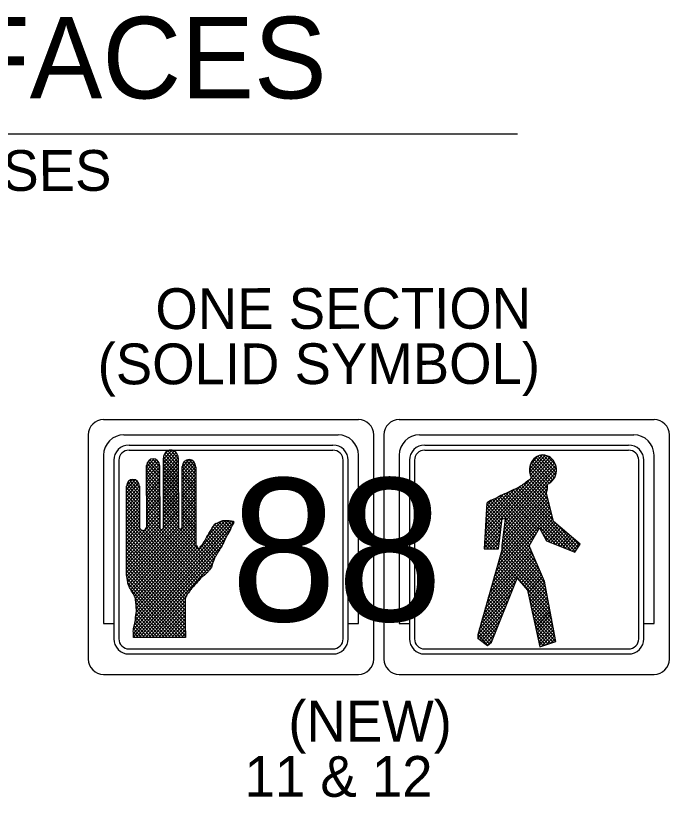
# Model space of a CAD drawing. Extents: x 110 to 419214, y -565865 to 630.
# Drawn here: x 379.5 to 443.6, y 366.9 to 443.6 of the extents above; entities that cross this region are included whole.
import ezdxf

# ---------------------------------------------------------------- set-up
doc = ezdxf.new("R2010")
doc.units = 0
doc.layers.add('T_Drafting', color=7, linetype='Continuous')
doc.layers.add('T_Notes', color=7, linetype='Continuous')

msp = doc.modelspace()

# ---------------------------------------------------------------- linework, layer by layer
at = {"layer": 'T_Drafting'}
for p, q in [((388.079, 403.971), (413.079, 403.971)), ((417.079, 403.971), (442.079, 403.971)), ((386.579, 402.471), (386.579, 380.471)), ((390.079, 402.471), (411.079, 402.471)), ((414.579, 380.471), (414.579, 402.471)), ((415.579, 402.471), (415.579, 380.471)), ((419.079, 402.471), (440.079, 402.471)), ((443.579, 380.471), (443.579, 402.471)), ((390.579, 401.471), (410.579, 401.471)), ((419.579, 401.471), (439.579, 401.471)), ((388.079, 400.471), (388.079, 383.971)), ((390.579, 400.971), (410.579, 400.971)), ((393.943, 400.055), (394.765, 400.968)), ((393.944, 399.702), (395.009, 400.885)), ((393.944, 399.349), (395.193, 400.737)), ((393.945, 398.996), (395.327, 400.532)), ((393.997, 400.468), (394.398, 400.914)), ((394.049, 400.583), (395.408, 399.073)), ((394.194, 400.775), (395.407, 399.427)), ((394.39, 400.911), (395.407, 399.781)), ((394.651, 400.974), (395.407, 400.135)), ((395.118, 400.809), (395.26, 400.652)), ((413.079, 383.971), (413.079, 400.471)), ((417.079, 400.471), (417.079, 383.971)), ((419.579, 400.971), (439.579, 400.971)), ((429.855, 399.119), (431.09, 400.492)), ((429.87, 398.782), (431.394, 400.475)), ((429.937, 398.503), (431.644, 400.4)), ((429.95, 399.578), (430.677, 400.386)), ((430.677, 400.386), (432.404, 398.467)), ((430.922, 400.467), (432.477, 398.739)), ((431.216, 400.494), (432.501, 399.066)), ((431.604, 400.416), (432.431, 399.498)), ((442.079, 383.971), (442.079, 400.471)), ((389.079, 399.971), (389.079, 382.471)), ((389.579, 399.971), (389.579, 382.471)), ((392.305, 399.296), (393.042, 400.115)), ((392.305, 398.942), (393.275, 400.019)), ((392.306, 398.589), (393.443, 399.853)), ((392.306, 398.236), (393.552, 399.62)), ((392.34, 399.653), (393.579, 398.276)), ((392.362, 399.713), (392.673, 400.058)), ((392.457, 399.877), (393.579, 398.63)), ((392.633, 400.035), (393.579, 398.984)), ((392.875, 400.12), (393.578, 399.338)), ((393.299, 400.001), (393.469, 399.813)), ((393.951, 393.371), (393.943, 400.198)), ((393.943, 399.993), (395.409, 398.365)), ((393.944, 399.639), (395.409, 398.011)), ((393.945, 398.643), (395.403, 400.262)), ((393.945, 398.29), (395.407, 399.914)), ((393.958, 400.33), (395.408, 398.719)), ((395.406, 400.217), (395.414, 393.439)), ((395.774, 399.26), (396.479, 400.044)), ((395.774, 398.907), (396.736, 399.976)), ((395.774, 398.554), (396.926, 399.833)), ((395.775, 398.201), (397.061, 399.63)), ((395.85, 399.642), (397.136, 398.214)), ((395.988, 399.842), (397.135, 398.568)), ((396.181, 399.982), (397.135, 398.922)), ((396.442, 400.045), (397.135, 399.276)), ((411.579, 382.471), (411.579, 399.971)), ((412.079, 382.471), (412.079, 399.971)), ((418.079, 399.971), (418.079, 382.471)), ((418.579, 399.971), (418.579, 382.471)), ((425.489, 392.501), (432.201, 399.958)), ((425.509, 392.876), (432.043, 400.136)), ((425.528, 393.251), (431.859, 400.285)), ((427.379, 394.247), (432.33, 399.748)), ((430.008, 399.715), (431.8, 397.723)), ((430.133, 399.93), (431.993, 397.863)), ((430.286, 400.113), (432.158, 398.033)), ((430.467, 400.266), (432.296, 398.234)), ((440.579, 382.471), (440.579, 399.971)), ((441.079, 382.471), (441.079, 399.971)), ((392.312, 393.498), (392.305, 399.463)), ((392.305, 399.339), (393.58, 397.922)), ((392.305, 398.985), (393.58, 397.568)), ((392.307, 397.883), (393.578, 399.296)), ((392.307, 397.53), (393.579, 398.943)), ((393.578, 399.449), (393.584, 393.403)), ((393.944, 399.285), (395.409, 397.657)), ((393.945, 398.931), (395.41, 397.303)), ((393.946, 397.937), (395.407, 399.561)), ((393.946, 397.583), (395.408, 399.207)), ((393.947, 397.23), (395.408, 398.854)), ((395.78, 393.406), (395.774, 399.354)), ((395.774, 399.02), (397.136, 397.506)), ((395.775, 399.372), (397.136, 397.86)), ((395.775, 397.848), (397.132, 399.356)), ((395.776, 397.495), (397.135, 399.005)), ((397.135, 399.307), (397.143, 391.65)), ((427.342, 393.145), (432.495, 398.87)), ((427.397, 393.559), (432.49, 399.219)), ((427.451, 393.973), (432.429, 399.504)), ((429.859, 399.174), (431.625, 397.212)), ((429.865, 398.813), (431.558, 396.932)), ((429.913, 399.467), (431.628, 397.561)), ((390.317, 397.44), (390.912, 398.102)), ((390.317, 397.087), (391.187, 398.054)), ((390.876, 398.098), (391.59, 397.304)), ((392.306, 398.631), (393.581, 397.214)), ((392.306, 398.277), (393.581, 396.86)), ((392.307, 397.177), (393.579, 398.59)), ((392.308, 396.824), (393.579, 398.237)), ((393.945, 398.577), (395.41, 396.949)), ((393.945, 398.223), (395.411, 396.595)), ((393.947, 396.877), (395.408, 398.501)), ((393.947, 396.524), (395.409, 398.148)), ((395.774, 398.666), (397.137, 397.152)), ((395.775, 398.312), (397.137, 396.798)), ((395.776, 397.142), (397.135, 398.652)), ((395.776, 396.789), (397.136, 398.299)), ((429.877, 398.093), (431.678, 396.092)), ((430.009, 398.3), (431.559, 396.578)), ((431.76, 397.701), (432.367, 398.374)), ((390.326, 389.2), (390.316, 397.443)), ((390.317, 397.305), (391.592, 395.888)), ((390.318, 396.734), (391.383, 397.918)), ((390.318, 396.381), (391.521, 397.717)), ((390.318, 396.028), (391.59, 397.44)), ((390.349, 397.623), (391.591, 396.242)), ((390.464, 397.849), (391.591, 396.596)), ((390.637, 398.01), (391.591, 396.95)), ((391.279, 398.004), (391.501, 397.757)), ((391.59, 397.428), (391.594, 393.497)), ((392.307, 397.923), (393.581, 396.506)), ((392.307, 397.569), (393.582, 396.152)), ((392.308, 396.471), (393.58, 397.884)), ((392.309, 396.118), (393.58, 397.531)), ((393.946, 397.869), (395.411, 396.241)), ((393.946, 397.515), (395.411, 395.887)), ((393.948, 396.171), (395.409, 397.795)), ((393.948, 395.818), (395.41, 397.442)), ((395.775, 397.958), (397.137, 396.444)), ((395.775, 397.604), (397.138, 396.09)), ((395.777, 396.435), (397.136, 397.946)), ((395.777, 396.082), (397.136, 397.593)), ((425.548, 393.626), (428.945, 397.401)), ((427.288, 392.731), (431.628, 397.554)), ((428.921, 397.387), (434.47, 391.222)), ((429.123, 397.517), (432.153, 394.149)), ((429.306, 397.666), (432.034, 394.635)), ((429.489, 397.817), (431.916, 395.121)), ((429.676, 397.962), (431.797, 395.606)), ((390.317, 396.951), (391.592, 395.534)), ((390.318, 396.597), (391.593, 395.18)), ((390.319, 395.674), (391.59, 397.087)), ((390.319, 395.321), (391.591, 396.734)), ((392.307, 397.215), (393.582, 395.798)), ((392.308, 396.861), (393.583, 395.444)), ((392.309, 395.765), (393.581, 397.177)), ((392.309, 395.411), (393.581, 396.824)), ((393.947, 397.161), (395.412, 395.533)), ((393.947, 396.807), (395.412, 395.179)), ((393.948, 395.465), (395.41, 397.089)), ((393.949, 395.112), (395.41, 396.736)), ((395.776, 397.25), (397.138, 395.736)), ((395.776, 396.896), (397.139, 395.382)), ((395.777, 396.542), (397.139, 395.028)), ((395.778, 395.729), (397.137, 397.239)), ((395.778, 395.376), (397.137, 396.886)), ((395.778, 395.023), (397.137, 396.533)), ((425.567, 394.001), (428.371, 397.117)), ((425.586, 394.376), (427.823, 396.862)), ((425.606, 394.752), (427.284, 396.616)), ((427.129, 396.55), (430.511, 392.792)), ((427.179, 391.903), (431.522, 396.729)), ((427.233, 392.317), (431.624, 397.196)), ((427.359, 396.648), (430.632, 393.011)), ((427.586, 396.749), (430.753, 393.231)), ((427.809, 396.855), (432.449, 391.699)), ((428.031, 396.962), (432.942, 391.505)), ((428.256, 397.066), (433.435, 391.311)), ((428.483, 397.167), (433.927, 391.118)), ((428.706, 397.272), (434.33, 391.024)), ((390.318, 396.243), (391.593, 394.826)), ((390.319, 395.889), (391.593, 394.472)), ((390.32, 394.968), (391.591, 396.381)), ((390.32, 394.615), (391.592, 396.028)), ((392.308, 396.507), (393.583, 395.09)), ((392.309, 396.153), (393.583, 394.736)), ((392.309, 395.799), (393.584, 394.382)), ((392.31, 395.058), (393.581, 396.471)), ((392.31, 394.705), (393.582, 396.118)), ((392.311, 394.352), (393.582, 395.765)), ((393.947, 396.453), (395.413, 394.825)), ((393.948, 396.099), (395.413, 394.471)), ((393.948, 395.745), (395.413, 394.117)), ((393.949, 394.759), (395.411, 396.382)), ((393.95, 394.405), (395.411, 396.029)), ((395.777, 396.188), (397.139, 394.674)), ((395.777, 395.834), (397.14, 394.32)), ((395.779, 394.67), (397.138, 396.18)), ((395.779, 394.317), (397.138, 395.827)), ((425.625, 395.127), (426.723, 396.346)), ((425.645, 395.502), (426.164, 396.078)), ((425.824, 395.879), (427.289, 394.251)), ((426.025, 396.009), (429.908, 391.694)), ((426.253, 396.109), (430.029, 391.914)), ((426.479, 396.211), (430.149, 392.133)), ((426.692, 396.329), (430.27, 392.353)), ((426.905, 396.445), (430.391, 392.572)), ((426.99, 390.632), (431.726, 395.895)), ((427.136, 391.149), (431.658, 396.173)), ((427.141, 391.507), (431.59, 396.451)), ((390.319, 395.535), (391.594, 394.118)), ((390.319, 395.181), (391.594, 393.764)), ((390.32, 394.262), (391.592, 395.675)), ((390.321, 393.909), (391.592, 395.322)), ((392.309, 395.445), (393.584, 394.028)), ((392.31, 395.091), (393.585, 393.674)), ((392.311, 393.999), (393.583, 395.412)), ((392.311, 393.646), (393.583, 395.059)), ((393.949, 395.391), (395.414, 393.763)), ((393.949, 395.037), (395.409, 393.415)), ((393.95, 394.052), (395.412, 395.676)), ((393.95, 393.699), (395.412, 395.323)), ((395.778, 395.48), (397.14, 393.966)), ((395.778, 395.126), (397.14, 393.612)), ((395.78, 393.964), (397.138, 395.474)), ((395.78, 393.611), (397.139, 395.12)), ((425.621, 395.043), (427.07, 393.434)), ((425.638, 395.378), (427.107, 393.746)), ((425.656, 395.712), (427.144, 394.058)), ((426.55, 389.083), (431.93, 395.061)), ((426.696, 389.599), (431.862, 395.339)), ((426.843, 390.116), (431.794, 395.617)), ((390.32, 394.827), (391.606, 393.398)), ((390.32, 394.473), (396.698, 387.387)), ((390.321, 393.556), (391.593, 394.969)), ((390.321, 393.202), (391.593, 394.616)), ((390.322, 392.849), (391.594, 394.263)), ((390.324, 391.084), (393.583, 394.706)), ((390.324, 390.731), (393.584, 394.353)), ((390.338, 388.978), (395.413, 394.617)), ((390.349, 388.637), (395.413, 394.264)), ((390.619, 387.522), (397.139, 394.767)), ((390.742, 387.306), (397.14, 394.414)), ((392.31, 394.737), (393.601, 393.303)), ((392.311, 394.383), (397.657, 388.442)), ((393.947, 393.342), (395.412, 394.97)), ((393.949, 394.683), (398.643, 389.468)), ((393.95, 394.329), (398.504, 389.269)), ((395.779, 394.772), (397.141, 393.258)), ((395.779, 394.418), (397.141, 392.905)), ((425.586, 394.375), (426.995, 392.81)), ((425.604, 394.709), (427.033, 393.122)), ((426.403, 388.566), (431.998, 394.783)), ((430.904, 393.214), (432.066, 394.505)), ((431.023, 392.992), (432.134, 394.227)), ((390.32, 394.119), (396.55, 387.197)), ((390.321, 393.765), (396.416, 386.993)), ((390.322, 392.496), (391.594, 393.909)), ((390.323, 392.143), (391.594, 393.556)), ((390.325, 390.377), (393.584, 393.999)), ((390.325, 390.024), (393.585, 393.646)), ((390.398, 388.338), (395.414, 393.911)), ((390.447, 388.039), (395.414, 393.558)), ((390.867, 387.091), (397.14, 394.061)), ((390.991, 386.875), (397.14, 393.708)), ((391.002, 382.998), (400.848, 393.938)), ((391.012, 383.363), (400.617, 394.035)), ((391.117, 383.833), (400.328, 394.068)), ((391.187, 384.265), (400.01, 394.068)), ((392.311, 394.029), (397.5, 388.263)), ((392.311, 393.675), (397.344, 388.083)), ((393.95, 393.975), (398.354, 389.082)), ((393.951, 393.621), (398.197, 388.903)), ((395.779, 394.064), (397.141, 392.551)), ((395.78, 393.71), (397.142, 392.197)), ((398.181, 392.389), (399.637, 394.007)), ((398.783, 393.411), (399.125, 393.791)), ((398.838, 393.494), (399.993, 392.211)), ((398.988, 393.68), (400.105, 392.44)), ((399.186, 393.815), (400.227, 392.658)), ((399.41, 393.919), (400.355, 392.869)), ((399.646, 394.011), (400.477, 393.087)), ((399.912, 394.068), (400.579, 393.328)), ((400.23, 394.068), (400.692, 393.556)), ((400.572, 394.042), (400.803, 393.786)), ((425.45, 391.75), (427.086, 393.567)), ((425.47, 392.125), (427.135, 393.975)), ((425.552, 393.706), (426.921, 392.185)), ((425.569, 394.041), (426.958, 392.497)), ((427.381, 393.441), (430.556, 389.913)), ((427.422, 393.75), (430.266, 390.59)), ((427.462, 394.058), (429.975, 391.267)), ((431.142, 392.771), (432.207, 393.955)), ((431.261, 392.549), (432.389, 393.803)), ((431.379, 392.328), (432.57, 393.65)), ((431.498, 392.106), (432.751, 393.498)), ((432.702, 393.54), (434.61, 391.419)), ((390.321, 393.411), (396.272, 386.799)), ((390.322, 393.057), (396.161, 386.569)), ((390.322, 392.703), (396.077, 386.309)), ((390.323, 391.79), (391.657, 393.273)), ((390.323, 391.437), (391.839, 393.12)), ((390.325, 389.671), (393.599, 393.308)), ((390.326, 389.318), (393.808, 393.188)), ((390.511, 387.756), (395.472, 393.268)), ((391.002, 382.645), (400.541, 393.244)), ((391.112, 386.656), (397.141, 393.355)), ((391.206, 386.407), (397.141, 393.002)), ((391.863, 393.113), (396.857, 387.563)), ((392.14, 393.158), (397.019, 387.737)), ((392.286, 393.35), (397.182, 387.909)), ((393.692, 393.201), (397.828, 388.605)), ((393.93, 393.291), (398.017, 388.75)), ((395.587, 393.217), (398.737, 389.717)), ((395.773, 393.364), (397.142, 391.843)), ((398.446, 392.869), (399.644, 391.538)), ((398.585, 393.067), (399.763, 391.759)), ((398.706, 393.287), (399.88, 391.982)), ((425.431, 391.375), (427.037, 393.16)), ((425.5, 392.703), (426.775, 391.287)), ((425.517, 393.038), (426.846, 391.561)), ((425.534, 393.372), (426.883, 391.873)), ((425.668, 391.285), (426.988, 392.752)), ((426.257, 388.05), (430.49, 392.754)), ((427.3, 392.824), (431.138, 388.56)), ((427.341, 393.133), (430.847, 389.237)), ((431.105, 392.839), (431.957, 391.893)), ((431.711, 391.989), (432.933, 393.346)), ((431.946, 391.897), (433.114, 393.194)), ((432.181, 391.804), (433.295, 393.042)), ((432.416, 391.712), (433.476, 392.89)), ((432.651, 391.62), (433.658, 392.738)), ((390.322, 392.349), (396.088, 385.943)), ((390.323, 391.995), (396.073, 385.605)), ((391.242, 386.093), (397.141, 392.648)), ((391.267, 382.586), (400.065, 392.362)), ((391.272, 385.774), (397.142, 392.295)), ((391.291, 385.441), (397.142, 391.942)), ((397.957, 391.998), (399.14, 390.684)), ((398.096, 392.197), (399.261, 390.902)), ((398.202, 392.433), (399.393, 391.11)), ((398.322, 392.653), (399.522, 391.32)), ((425.465, 392.035), (426.139, 391.286)), ((425.482, 392.369), (426.457, 391.286)), ((425.987, 391.286), (426.94, 392.344)), ((426.305, 391.286), (426.891, 391.937)), ((427.219, 392.208), (431.45, 387.506)), ((427.259, 392.516), (431.366, 387.953)), ((432.886, 391.527), (433.839, 392.586)), ((433.121, 391.435), (434.02, 392.434)), ((433.356, 391.342), (434.202, 392.281)), ((433.591, 391.25), (434.383, 392.129)), ((433.826, 391.157), (434.564, 391.977)), ((434.002, 392.449), (434.75, 391.617)), ((390.323, 391.641), (396.074, 385.251)), ((390.324, 391.287), (396.09, 384.88)), ((391.232, 384.669), (397.304, 391.415)), ((391.288, 385.085), (397.188, 391.639)), ((391.586, 382.586), (399.647, 391.543)), ((397.527, 391.415), (398.819, 389.98)), ((397.676, 391.604), (398.913, 390.228)), ((397.824, 391.793), (399.021, 390.462)), ((425.431, 391.366), (425.503, 391.285)), ((425.448, 391.7), (425.821, 391.285)), ((425.817, 386.501), (430.017, 391.168)), ((425.963, 387.017), (429.914, 391.407)), ((426.11, 387.533), (429.991, 391.846)), ((426.624, 391.287), (426.842, 391.529)), ((426.757, 391.291), (426.811, 391.351)), ((427.14, 391.587), (431.617, 386.613)), ((427.141, 391.233), (431.701, 386.167)), ((427.178, 391.899), (431.534, 387.06)), ((434.061, 391.065), (434.745, 391.825)), ((390.324, 390.933), (396.092, 384.524)), ((390.324, 390.579), (396.092, 384.17)), ((391.904, 382.587), (399.065, 390.543)), ((425.377, 384.951), (430.326, 390.45)), ((425.524, 385.468), (430.223, 390.689)), ((425.67, 385.984), (430.12, 390.929)), ((426.927, 390.411), (431.952, 384.827)), ((427.003, 390.68), (431.868, 385.274)), ((427.079, 390.948), (431.785, 385.72)), ((390.325, 390.225), (396.093, 383.816)), ((390.325, 389.871), (396.095, 383.46)), ((392.223, 382.587), (398.782, 389.875)), ((426.774, 389.873), (428.472, 387.986)), ((426.85, 390.142), (428.57, 388.231)), ((428.722, 388.315), (430.429, 390.211)), ((428.879, 388.135), (430.531, 389.971)), ((429.035, 387.955), (430.634, 389.732)), ((390.325, 389.517), (396.109, 383.091)), ((390.328, 389.161), (396.129, 382.715)), ((426.545, 389.067), (428.179, 387.251)), ((426.622, 389.336), (428.277, 387.496)), ((426.698, 389.604), (428.375, 387.741)), ((429.192, 387.775), (430.737, 389.493)), ((429.348, 387.596), (430.84, 389.253)), ((429.504, 387.416), (430.943, 389.014)), ((390.34, 388.794), (395.922, 382.592)), ((390.39, 388.385), (395.604, 382.592)), ((425.23, 384.435), (428.509, 388.077)), ((426.316, 388.26), (427.886, 386.517)), ((426.393, 388.529), (427.984, 386.762)), ((426.469, 388.798), (428.081, 387.007)), ((429.661, 387.236), (431.046, 388.775)), ((429.725, 386.953), (431.148, 388.536)), ((429.787, 386.669), (431.251, 388.296)), ((390.462, 387.951), (395.286, 382.591)), ((425.084, 383.918), (428.255, 387.442)), ((426.087, 387.454), (427.593, 385.782)), ((426.164, 387.723), (427.69, 386.027)), ((426.24, 387.992), (427.788, 386.272)), ((429.849, 386.384), (431.348, 388.05)), ((429.911, 386.1), (431.403, 387.758)), ((429.973, 385.815), (431.458, 387.465)), ((390.773, 387.252), (394.968, 382.591)), ((392.541, 382.588), (396.214, 386.669)), ((424.937, 383.402), (428.002, 386.807)), ((425.859, 386.648), (427.299, 385.047)), ((425.935, 386.917), (427.397, 385.292)), ((426.011, 387.185), (427.495, 385.537)), ((429.726, 386.947), (432.035, 384.381)), ((430.035, 385.53), (431.513, 387.172)), ((430.097, 385.246), (431.567, 386.88)), ((430.159, 384.961), (431.622, 386.587)), ((391.204, 386.42), (394.65, 382.591)), ((391.25, 386.015), (394.333, 382.59)), ((392.86, 382.588), (396.084, 386.17)), ((393.179, 382.588), (396.081, 385.814)), ((424.791, 382.886), (427.748, 386.172)), ((425.63, 385.841), (427.006, 384.312)), ((425.706, 386.11), (427.104, 384.557)), ((425.782, 386.379), (427.202, 384.802)), ((429.828, 386.48), (432.119, 383.934)), ((429.929, 386.014), (432.203, 383.488)), ((430.221, 384.676), (431.677, 386.294)), ((430.283, 384.392), (431.732, 386.002)), ((391.282, 385.626), (394.015, 382.59)), ((391.294, 385.259), (393.697, 382.589)), ((393.497, 382.589), (396.072, 385.45)), ((393.816, 382.589), (396.08, 385.105)), ((424.78, 382.52), (427.495, 385.536)), ((425.401, 385.035), (426.713, 383.577)), ((425.477, 385.304), (426.811, 383.822)), ((425.553, 385.573), (426.908, 384.067)), ((430.031, 385.547), (432.286, 383.041)), ((430.133, 385.081), (432.37, 382.595)), ((430.345, 384.107), (431.787, 385.709)), ((430.407, 383.823), (431.841, 385.416)), ((430.469, 383.538), (431.896, 385.124)), ((391.192, 384.312), (392.744, 382.588)), ((391.227, 384.627), (393.061, 382.588)), ((391.273, 384.929), (393.379, 382.589)), ((394.134, 382.59), (396.092, 384.765)), ((394.453, 382.59), (396.092, 384.412)), ((424.968, 382.375), (427.241, 384.901)), ((425.156, 382.23), (426.988, 384.266)), ((425.248, 384.498), (426.517, 383.087)), ((425.325, 384.766), (426.615, 383.332)), ((430.234, 384.614), (432.412, 382.194)), ((430.531, 383.253), (431.951, 384.831)), ((430.593, 382.969), (432.006, 384.539)), ((430.655, 382.684), (432.061, 384.246)), ((388.079, 383.971), (389.079, 383.971)), ((391.082, 383.727), (392.108, 382.587)), ((391.157, 383.998), (392.426, 382.587)), ((394.772, 382.591), (396.093, 384.058)), ((395.09, 382.591), (396.093, 383.705)), ((412.079, 383.971), (413.079, 383.971)), ((417.079, 383.971), (418.079, 383.971)), ((425.019, 383.691), (426.224, 382.353)), ((425.096, 383.96), (426.322, 382.598)), ((425.172, 384.229), (426.42, 382.842)), ((425.344, 382.086), (426.734, 383.631)), ((430.336, 384.148), (432.168, 382.112)), ((430.438, 383.681), (431.924, 382.03)), ((430.717, 382.399), (432.116, 383.953)), ((430.779, 382.115), (432.17, 383.661)), ((441.079, 383.971), (442.079, 383.971)), ((391.002, 382.755), (391.155, 382.586)), ((391.003, 383.108), (391.472, 382.586)), ((391.017, 383.445), (391.79, 382.587)), ((395.409, 382.592), (396.098, 383.357)), ((395.727, 382.592), (396.113, 383.02)), ((424.79, 382.885), (425.756, 381.812)), ((424.867, 383.154), (425.94, 381.961)), ((424.943, 383.422), (426.123, 382.111)), ((425.532, 381.941), (426.481, 382.996)), ((430.54, 383.215), (431.68, 381.947)), ((430.641, 382.748), (431.436, 381.865)), ((430.841, 381.83), (432.225, 383.368)), ((431.084, 381.746), (432.28, 383.075)), ((431.541, 381.9), (432.335, 382.783)), ((391.027, 382.585), (391.002, 382.617)), ((396.107, 382.593), (391.027, 382.585)), ((396.046, 382.592), (396.129, 382.685)), ((396.13, 382.587), (396.107, 382.593)), ((424.769, 382.528), (424.796, 382.528)), ((424.779, 382.544), (424.849, 382.466)), ((425.72, 381.796), (426.227, 382.36)), ((426.119, 382.11), (426.119, 382.11)), ((430.743, 382.281), (431.192, 381.783)), ((431.998, 382.054), (432.39, 382.49)), ((390.579, 381.471), (410.579, 381.471)), ((419.579, 381.471), (439.579, 381.471)), ((430.845, 381.815), (430.948, 381.7)), ((390.579, 380.971), (410.579, 380.971)), ((419.579, 380.971), (439.579, 380.971)), ((388.079, 378.971), (413.079, 378.971)), ((417.079, 378.971), (442.079, 378.971))]:
    msp.add_line(p, q, dxfattribs=at)
msp.add_lwpolyline([(425.659, 395.773), (425.426, 391.285), (426.813, 391.287), (427.168, 394.255), (427.487, 394.243), (427.14, 391.612), (427.141, 391.165), (424.779, 382.844), (424.779, 382.52), (425.729, 381.789), (426.13, 382.116), (428.641, 388.408), (429.664, 387.233), (430.875, 381.676), (432.443, 382.205), (431.341, 388.087), (429.842, 391.575), (430.825, 393.362), (431.52, 392.064), (434.294, 390.973), (434.841, 391.745), (432.199, 393.961), (431.513, 396.764), (431.624, 397.178), (431.629, 397.629), (431.769, 397.705)], dxfattribs=at)
for centre, radius, start, end in [((388.079, 402.471), 1.5, 90, 180), ((413.079, 402.471), 1.5, 360, 90), ((417.079, 402.471), 1.5, 90, 180), ((442.079, 402.471), 1.5, 360, 90), ((390.079, 400.471), 2, 90, 180), ((411.079, 400.471), 2, 360, 90), ((419.079, 400.471), 2, 90, 180), ((440.079, 400.471), 2, 360, 90), ((390.579, 399.971), 1.5, 90, 180), ((410.579, 399.971), 1.5, 360, 90), ((419.579, 399.971), 1.5, 90, 180), ((439.579, 399.971), 1.5, 360, 90), ((390.579, 399.971), 1, 90, 180), ((410.579, 399.971), 1, 360, 90), ((419.579, 399.971), 1, 90, 180), ((439.579, 399.971), 1, 360, 90), ((390.579, 382.471), 1.5, 180, 270), ((390.579, 382.471), 1, 180, 270), ((410.579, 382.471), 1.5, 270, 360), ((410.579, 382.471), 1, 270, 360), ((419.579, 382.471), 1.5, 180, 270), ((419.579, 382.471), 1, 180, 270), ((439.579, 382.471), 1.5, 270, 360), ((439.579, 382.471), 1, 270, 360), ((388.079, 380.471), 1.5, 180, 270), ((413.079, 380.471), 1.5, 270, 360), ((417.079, 380.471), 1.5, 180, 270), ((442.079, 380.471), 1.5, 270, 360)]:
    msp.add_arc(centre, radius, start, end, dxfattribs=at)
for centre, major_axis, start_param, end_param in [((394.675, 400.16), (0, -0.814), 1.640121, 4.665593), ((431.177, 399.023), (0, -1.472), 0.463156, 5.216339), ((392.941, 399.415), (0, -0.709), 1.618611, 4.644084), ((396.453, 399.287), (0, -0.758), 1.597842, 4.623315), ((390.953, 397.395), (0, -0.709), 1.618611, 4.644084), ((391.953, 393.498), (0, -0.398), 4.713646, 7.855239), ((395.595, 393.424), (0, -0.207), 4.624552, 7.766145), ((393.768, 393.387), (0, -0.204), 4.633755, 7.775348)]:
    msp.add_ellipse(centre, major_axis=major_axis, ratio=0.9, start_param=start_param, end_param=end_param, dxfattribs=at)
for points in [[(430.016, 398.311), (429.863, 398.072), (429.651, 397.946), (429.397, 397.742), (429.109, 397.507), (428.048, 396.97), (427.537, 396.726), (427.037, 396.509), (426.37, 396.155), (426.047, 396.023), (425.659, 395.773)], [(397.142, 391.651), (397.194, 391.637), (397.263, 391.482), (397.351, 391.363), (397.404, 391.344), (397.491, 391.364), (397.545, 391.444), (397.703, 391.638), (397.826, 391.796), (397.896, 391.912), (397.966, 392.01), (398.089, 392.186), (398.159, 392.343), (398.265, 392.558), (398.335, 392.676), (398.459, 392.89), (398.598, 393.087), (398.704, 393.282), (398.826, 393.477), (398.933, 393.615), (399.089, 393.772), (399.283, 393.851), (399.389, 393.91), (399.547, 393.967), (399.688, 394.028), (399.9, 394.068), (400.075, 394.068), (400.304, 394.068), (400.516, 394.049), (400.761, 394.01), (400.832, 393.969), (400.848, 393.912), (400.745, 393.658), (400.674, 393.52), (400.604, 393.382), (400.534, 393.227), (400.498, 393.129), (400.358, 392.874), (400.148, 392.522), (399.866, 391.955), (399.515, 391.307), (399.235, 390.857), (399.076, 390.564), (398.937, 390.289), (398.854, 390.071), (398.811, 389.96), (398.654, 389.488), (398.41, 389.155), (398.216, 388.921), (397.935, 388.684), (397.759, 388.547), (397.302, 388.037), (396.899, 387.608), (396.635, 387.313), (396.406, 386.979), (396.292, 386.834), (396.196, 386.629), (396.09, 386.432), (396.09, 386.002), (396.074, 385.616), (396.074, 385.262), (396.092, 384.794), (396.092, 384.344), (396.093, 383.62), (396.112, 383.037), (396.129, 382.821), (396.129, 382.663), (396.129, 382.588)], [(391.002, 382.617), (391.002, 382.931), (391.018, 383.458), (391.158, 384.007), (391.227, 384.633), (391.28, 384.985), (391.279, 385.67), (391.226, 386.237), (391.172, 386.53), (390.909, 387.018), (390.627, 387.508), (390.468, 387.919), (390.396, 388.349), (390.343, 388.682), (390.342, 388.896), (390.326, 389.2)]]:
    msp.add_spline(points, degree=3, dxfattribs=at)
at = {"layer": 'T_Notes'}
msp.add_line((330.484, 432.011), (428.669, 432.011), dxfattribs=at)

# ---------------------------------------------------------------- texts
at = {"layer": 'T_Drafting'}
for s, height, p in [('12" LENSES', 4, (358.41, 426.377)), ('ONE SECTION', 4, (393.165, 412.849)), ('(SOLID SYMBOL)', 4, (387.499, 407.423)), ('88', 14, (400.544, 384.192))]:
    msp.add_text(s, height=height, rotation=0.07203, dxfattribs=at).set_placement(p)
at = {"layer": 'T_Notes'}
for s, height, p in [('SIGNAL FACES', 8, (332.083, 435.48)), ('(NEW)', 4, (406.201, 372.38)), ('11 & 12', 4, (401.911, 366.962))]:
    msp.add_text(s, height=height, rotation=360, dxfattribs=at).set_placement(p)

doc.saveas('drawing.dxf')
